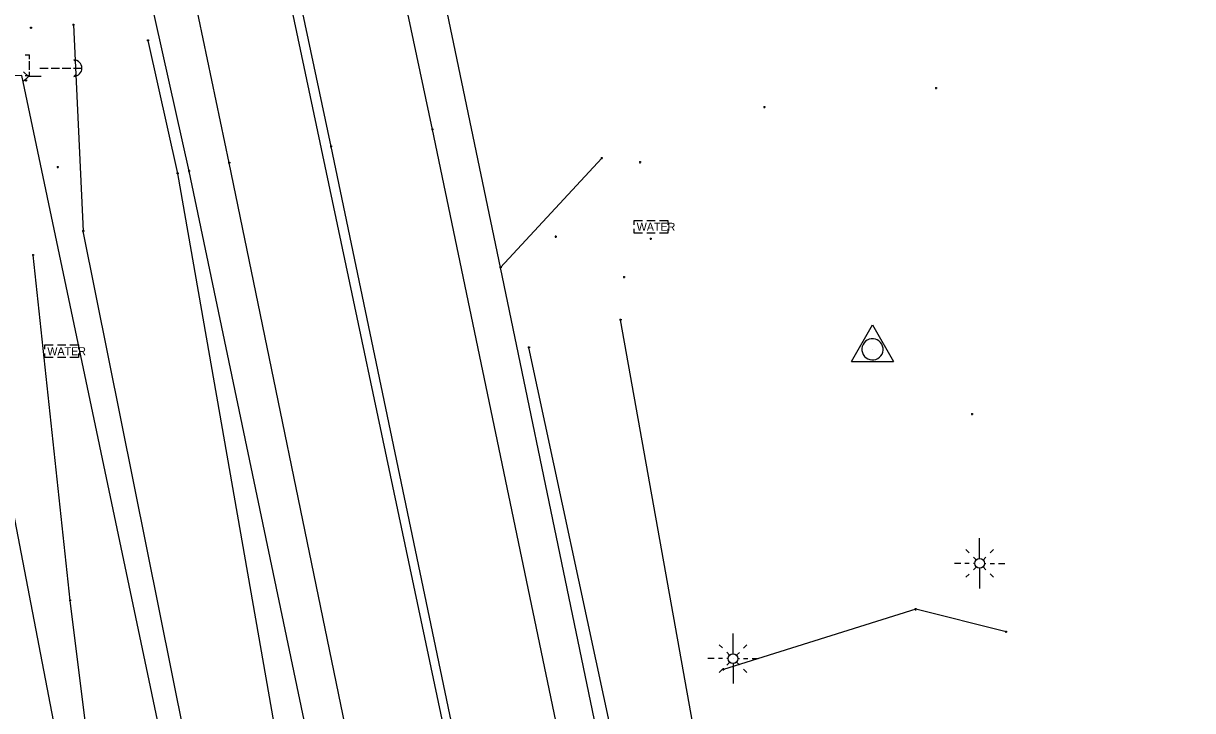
# Model space of a CAD drawing. Extents: x 1954856 to 2011933, y 399149 to 426294.
# Drawn here: x 2005312.9 to 2005451.7, y 406248.9 to 406330.4 of the extents above; entities that cross this region are included whole.
import ezdxf

# ---------------------------------------------------------------- set-up
doc = ezdxf.new("R2010")
doc.units = 0
for name, color, linetype in [('BankMent_ep', 7, 'Continuous'), ('BaselineSurvey', 7, 'Continuous'), ('Driveway_ep', 7, 'Continuous'), ('ElecAer_ep', 7, 'Continuous'), ('GuyWireAnchor_ep', 7, 'Continuous'), ('MeterWater_ep', 7, 'Continuous'), ('MonumentIRC_ep', 7, 'Continuous'), ('PavtAsphalt_ep', 7, 'Continuous'), ('PavtAsphaltCrown_ep', 7, 'Continuous'), ('PointLocator_ep', 7, 'Continuous'), ('PoleShared_ep', 7, 'Continuous'), ('ShldrPaved_ep', 7, 'Continuous'), ('ShrubHedge_ep', 7, 'Continuous'), ('Sprinkler_ep', 7, 'Continuous'), ('TelePed_ep', 7, 'Continuous'), ('TreeLineScatter_ep', 7, 'Continuous')]:
    doc.layers.add(name, color=color, linetype=linetype)

msp = doc.modelspace()

# ---------------------------------------------------------------- linework, layer by layer
at = {"layer": 'BankMent_ep'}
for p, q in [((2005331.26, 406312.62), (2005327.73, 406328.4)), ((2005346.47, 406225.8), (2005331.26, 406312.62)), ((2005333.75, 406237.64), (2005320.05, 406305.78)), ((2005318.48, 406261.94), (2005314.09, 406302.92)), ((2005396.71, 406223.34), (2005383.83, 406295.25)), ((2005388.07, 406221.54), (2005372.95, 406291.96)), ((2005324.23, 406216.02), (2005318.48, 406261.94))]:
    msp.add_line(p, q, dxfattribs=at)
msp.add_lwpolyline([(2005318.89, 406330.27), (2005320.05, 406305.78)], dxfattribs=at)
at = {"layer": 'BaselineSurvey'}
msp.add_line((2006223.92, 402174.38), (2005094.48, 407516.05), dxfattribs=at)
msp.add_line((2006223.92, 402174.38), (2005094.48, 407516.05), dxfattribs=at)
at = {"layer": 'Driveway_ep'}
msp.add_line((2005369.59, 406301.46), (2005381.59, 406314.46), dxfattribs=at)
at = {"layer": 'ElecAer_ep'}
msp.add_lwpolyline([(2005374.4, 406031.29), (2005312.74, 406324.27), (2005138.4, 406319.65)], dxfattribs=at)
at = {"layer": 'GuyWireAnchor_ep'}
for p, q in [((2005314.89, 406325.14), (2005315.89, 406325.14)), ((2005316.23, 406325.14), (2005317.23, 406325.14)), ((2005317.56, 406325.14), (2005318.56, 406325.14)), ((2005318.9, 406325.13), (2005319.9, 406325.13)), ((2005318.92, 406326.1), (2005319.11, 406325.91)), ((2005319.9, 406325.13), (2005319.9, 406325.13)), ((2005318.94, 406324.16), (2005319.17, 406324.39))]:
    msp.add_line(p, q, dxfattribs=at)
msp.add_arc((2005318.92, 406325.13), 0.973, 271.14, 90.0059, dxfattribs=at)
at = {"layer": 'MeterWater_ep'}
for p, q in [((2005387.43, 406306.29), (2005387.43, 406306.29)), ((2005317.47, 406291.52), (2005317.47, 406291.52))]:
    msp.add_line(p, q, dxfattribs=at)
for points in [[(2005385.43, 406306.54), (2005385.43, 406307.04), (2005386.43, 406307.04)], [(2005386.93, 406307.04), (2005387.93, 406307.04)], [(2005388.43, 406307.04), (2005389.43, 406307.04), (2005389.43, 406306.54)], [(2005386.43, 406305.54), (2005385.43, 406305.54), (2005385.43, 406306.04)], [(2005387.93, 406305.54), (2005386.93, 406305.54)], [(2005389.43, 406306.04), (2005389.43, 406305.54), (2005388.43, 406305.54)], [(2005315.47, 406291.77), (2005315.47, 406292.27), (2005316.47, 406292.27)], [(2005316.97, 406292.27), (2005317.97, 406292.27)], [(2005318.47, 406292.27), (2005319.47, 406292.27), (2005319.47, 406291.77)], [(2005316.47, 406290.77), (2005315.47, 406290.77), (2005315.47, 406291.27)], [(2005317.97, 406290.77), (2005316.97, 406290.77)], [(2005319.47, 406291.27), (2005319.47, 406290.77), (2005318.47, 406290.77)]]:
    msp.add_lwpolyline(points, dxfattribs=at)
at = {"layer": 'MonumentIRC_ep'}
for p, q in [((2005411.23, 406290.31), (2005413.73, 406294.64)), ((2005413.73, 406294.64), (2005416.23, 406290.31)), ((2005413.73, 406291.75), (2005413.73, 406291.75)), ((2005411.23, 406290.31), (2005416.23, 406290.31))]:
    msp.add_line(p, q, dxfattribs=at)
msp.add_arc((2005413.73, 406291.75), 1.26, 209.9294, 209.03, dxfattribs=at)
at = {"layer": 'PavtAsphalt_ep'}
for p, q in [((2005361.51, 406317.83), (2005340.77, 406415.41)), ((2005337.38, 406313.9), (2005316.85, 406411.1)), ((2005381.93, 406219.94), (2005361.51, 406317.83)), ((2005357.7, 406215.11), (2005337.38, 406313.9))]:
    msp.add_line(p, q, dxfattribs=at)
at = {"layer": 'PavtAsphaltCrown_ep'}
for p, q in [((2005349.48, 406315.81), (2005328.66, 406413.4)), ((2005369.98, 406217.68), (2005349.48, 406315.81))]:
    msp.add_line(p, q, dxfattribs=at)
at = {"layer": 'PointLocator_ep'}
for p, q in [((2005313.97, 406329.92), (2005313.72, 406329.92)), ((2005313.85, 406329.8), (2005313.85, 406330.05)), ((2005313.85, 406329.92), (2005313.85, 406329.92)), ((2005319.01, 406330.27), (2005318.76, 406330.27)), ((2005318.89, 406330.15), (2005318.89, 406330.4)), ((2005318.89, 406330.27), (2005318.89, 406330.27)), ((2005327.85, 406328.4), (2005327.6, 406328.4)), ((2005327.73, 406328.28), (2005327.73, 406328.53)), ((2005327.73, 406328.4), (2005327.73, 406328.4)), ((2005313.37, 406323.65), (2005313.12, 406323.65)), ((2005313.25, 406323.53), (2005313.25, 406323.78)), ((2005313.25, 406323.65), (2005313.25, 406323.65)), ((2005421.42, 406322.75), (2005421.17, 406322.75)), ((2005421.3, 406322.62), (2005421.3, 406322.87)), ((2005421.3, 406322.75), (2005421.3, 406322.75)), ((2005401.03, 406320.5), (2005400.78, 406320.5)), ((2005400.91, 406320.38), (2005400.91, 406320.63)), ((2005400.91, 406320.5), (2005400.91, 406320.5)), ((2005361.51, 406317.71), (2005361.51, 406317.96)), ((2005361.63, 406317.83), (2005361.38, 406317.83)), ((2005361.51, 406317.83), (2005361.51, 406317.83)), ((2005349.6, 406315.81), (2005349.35, 406315.81)), ((2005349.48, 406315.69), (2005349.48, 406315.94)), ((2005349.48, 406315.81), (2005349.48, 406315.81)), ((2005337.51, 406313.9), (2005337.26, 406313.9)), ((2005337.38, 406313.77), (2005337.38, 406314.02)), ((2005337.38, 406313.9), (2005337.38, 406313.9)), ((2005381.72, 406314.46), (2005381.47, 406314.46)), ((2005381.59, 406314.33), (2005381.59, 406314.58)), ((2005381.59, 406314.46), (2005381.59, 406314.46)), ((2005386.28, 406313.95), (2005386.03, 406313.95)), ((2005386.15, 406313.83), (2005386.15, 406314.08)), ((2005386.15, 406313.95), (2005386.15, 406313.95)), ((2005317.16, 406313.37), (2005316.91, 406313.37)), ((2005317.03, 406313.25), (2005317.03, 406313.5)), ((2005317.03, 406313.37), (2005317.03, 406313.37)), ((2005331.38, 406312.62), (2005331.13, 406312.62)), ((2005331.26, 406312.5), (2005331.26, 406312.75)), ((2005331.26, 406312.62), (2005331.26, 406312.62)), ((2005332.73, 406312.92), (2005332.48, 406312.92)), ((2005332.61, 406312.79), (2005332.61, 406313.04)), ((2005332.61, 406312.92), (2005332.61, 406312.92)), ((2005320.18, 406305.78), (2005319.93, 406305.78)), ((2005320.05, 406305.65), (2005320.05, 406305.9)), ((2005320.05, 406305.78), (2005320.05, 406305.78)), ((2005376.26, 406305.12), (2005376.01, 406305.12)), ((2005376.13, 406305), (2005376.13, 406305.25)), ((2005376.13, 406305.12), (2005376.13, 406305.12)), ((2005387.54, 406304.86), (2005387.29, 406304.86)), ((2005387.41, 406304.74), (2005387.41, 406304.99)), ((2005387.41, 406304.86), (2005387.41, 406304.86)), ((2005314.22, 406302.92), (2005313.97, 406302.92)), ((2005314.09, 406302.8), (2005314.09, 406303.05)), ((2005314.09, 406302.92), (2005314.09, 406302.92)), ((2005369.72, 406301.46), (2005369.47, 406301.46)), ((2005369.59, 406301.34), (2005369.59, 406301.59)), ((2005369.59, 406301.46), (2005369.59, 406301.46)), ((2005384.39, 406300.3), (2005384.14, 406300.3)), ((2005384.26, 406300.18), (2005384.26, 406300.43)), ((2005384.26, 406300.3), (2005384.26, 406300.3)), ((2005383.96, 406295.25), (2005383.71, 406295.25)), ((2005383.83, 406295.13), (2005383.83, 406295.38)), ((2005383.83, 406295.25), (2005383.83, 406295.25)), ((2005373.08, 406291.96), (2005372.83, 406291.96)), ((2005372.95, 406291.84), (2005372.95, 406292.09)), ((2005372.95, 406291.96), (2005372.95, 406291.96)), ((2005425.68, 406284.06), (2005425.43, 406284.06)), ((2005425.55, 406283.93), (2005425.55, 406284.18)), ((2005425.55, 406284.06), (2005425.55, 406284.06)), ((2005318.61, 406261.94), (2005318.36, 406261.94)), ((2005318.48, 406261.82), (2005318.48, 406262.07)), ((2005318.48, 406261.94), (2005318.48, 406261.94)), ((2005418.98, 406260.88), (2005418.73, 406260.88)), ((2005418.86, 406260.75), (2005418.86, 406261)), ((2005418.86, 406260.88), (2005418.86, 406260.88)), ((2005429.6, 406258.07), (2005429.6, 406258.32)), ((2005429.72, 406258.19), (2005429.47, 406258.19)), ((2005429.6, 406258.19), (2005429.6, 406258.19)), ((2005396.18, 406253.75), (2005395.93, 406253.75)), ((2005396.06, 406253.63), (2005396.06, 406253.88)), ((2005396.06, 406253.75), (2005396.06, 406253.75))]:
    msp.add_line(p, q, dxfattribs=at)
at = {"layer": 'PoleShared_ep'}
msp.add_line((2005315.03, 406324.14), (2005313.53, 406324.14), dxfattribs=at)
msp.add_lwpolyline([(2005312.97, 406324.71), (2005313.53, 406324.14), (2005312.97, 406323.57)], dxfattribs=at)
at = {"layer": 'ShldrPaved_ep'}
for points in [[(2005427.7, 406024.97), (2005407.05, 406122.81), (2005403.17, 406140.91), (2005394.43, 406182.67), (2005386.26, 406221.03), (2005369.59, 406301.46), (2005360.38, 406345.51), (2005345.13, 406416.29), (2005324.23, 406514.8), (2005303.28, 406612.46), (2005282.99, 406710.33), (2005262.63, 406808.01), (2005242.11, 406905.6)], [(2005394.47, 406019.03), (2005373.39, 406116.63), (2005368.48, 406141.45), (2005353.83, 406211.62), (2005332.61, 406312.92), (2005327.02, 406337.91), (2005318.05, 406379.99), (2005311.74, 406410.14), (2005291.04, 406507.65), (2005270.49, 406605.83), (2005262.78, 406641.74), (2005258.18, 406663.71), (2005249.81, 406703.72), (2005229.26, 406801.09), (2005208.4, 406899.51)]]:
    msp.add_lwpolyline(points, dxfattribs=at)
at = {"layer": 'ShrubHedge_ep'}
msp.add_lwpolyline([(2005429.6, 406258.19), (2005418.86, 406260.88), (2005396.06, 406253.75)], dxfattribs=at)
at = {"layer": 'Sprinkler_ep'}
for p, q in [((2005424.81, 406267.98), (2005425.2, 406267.58)), ((2005426.45, 406266.91), (2005426.45, 406269.31)), ((2005427.7, 406267.58), (2005428.09, 406267.98)), ((2005425.7, 406267.08), (2005426.04, 406266.74)), ((2005426.87, 406266.72), (2005427.2, 406267.06)), ((2005424.2, 406266.33), (2005423.48, 406266.33)), ((2005425.2, 406266.33), (2005424.7, 406266.33)), ((2005425.88, 406266.33), (2005425.7, 406266.33)), ((2005426.06, 406265.91), (2005425.7, 406265.56)), ((2005426.45, 406266.33), (2005426.45, 406266.33)), ((2005426.45, 406265.76), (2005426.45, 406263.36)), ((2005426.86, 406265.92), (2005427.2, 406265.58)), ((2005427.03, 406266.33), (2005427.2, 406266.33)), ((2005427.7, 406266.33), (2005428.2, 406266.33)), ((2005428.7, 406266.33), (2005429.43, 406266.33)), ((2005425.2, 406265.07), (2005424.81, 406264.68)), ((2005427.7, 406265.08), (2005428.09, 406264.68)), ((2005397.18, 406255.61), (2005397.18, 406258.01)), ((2005395.54, 406256.68), (2005395.93, 406256.29)), ((2005396.43, 406255.78), (2005396.77, 406255.44)), ((2005397.6, 406255.43), (2005397.93, 406255.76)), ((2005398.43, 406256.28), (2005398.82, 406256.68)), ((2005394.93, 406255.03), (2005394.2, 406255.03)), ((2005395.93, 406255.03), (2005395.43, 406255.03)), ((2005396.6, 406255.03), (2005396.43, 406255.03)), ((2005396.78, 406254.61), (2005396.43, 406254.26)), ((2005397.18, 406255.03), (2005397.18, 406255.03)), ((2005397.18, 406254.46), (2005397.18, 406252.06)), ((2005397.58, 406254.62), (2005397.93, 406254.28)), ((2005397.75, 406255.03), (2005397.93, 406255.03)), ((2005398.43, 406255.03), (2005398.93, 406255.03)), ((2005399.43, 406255.03), (2005400.15, 406255.03)), ((2005395.93, 406253.77), (2005395.54, 406253.38)), ((2005398.43, 406253.78), (2005398.82, 406253.38))]:
    msp.add_line(p, q, dxfattribs=at)
for centre in [(2005426.45, 406266.33), (2005397.18, 406255.03)]:
    msp.add_circle(centre, 0.575, dxfattribs=at)
at = {"layer": 'TelePed_ep'}
for p, q in [((2005313.16, 406326.7), (2005313.66, 406326.7)), ((2005313.66, 406326.2), (2005313.66, 406326.7)), ((2005313.66, 406324.95), (2005313.66, 406325.95)), ((2005313.66, 406324.2), (2005313.16, 406324.2)), ((2005313.66, 406324.2), (2005313.66, 406324.7))]:
    msp.add_line(p, q, dxfattribs=at)
at = {"layer": 'TreeLineScatter_ep'}
msp.add_lwpolyline([(2005327.42, 406190.8), (2005303.31, 406316.3), (2005168.97, 406319.99)], dxfattribs=at)

# ---------------------------------------------------------------- texts
at = {"layer": 'MeterWater_ep'}
for p in [(2005385.74, 406305.82), (2005315.78, 406291.05)]:
    msp.add_text('WATER', height=0.95, dxfattribs=at).set_placement(p)

doc.saveas('drawing.dxf')
